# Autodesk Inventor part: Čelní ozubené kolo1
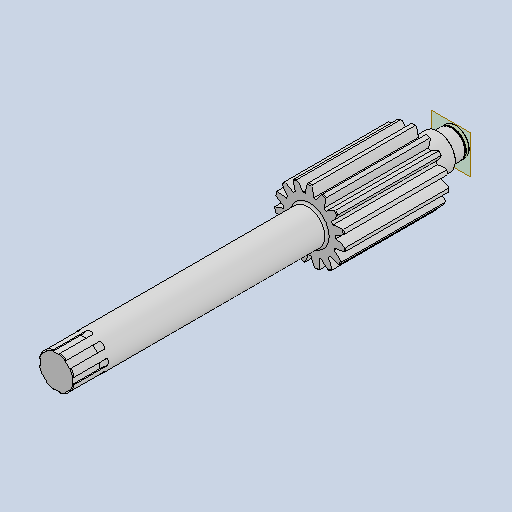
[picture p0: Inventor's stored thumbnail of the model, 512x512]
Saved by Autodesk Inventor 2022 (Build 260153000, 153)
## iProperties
CustomPartVersion: 1
Created: 2025-05
Part Number: Čelní ozubené kolo1
Material: Všeobecné
Document SubType Name: Modeling
Designer: jbart
Categories: <?xml version="1.0" encoding="UTF-16"?> <MemberInstance><Categories><FamilyTemplate><FamilyTemplateParameter ValueType="xs:double" Id="1" ObjectReferenceKey="da
Density: 1 g/cm^3
Appearance: Výchozí
Mass: 1756.11 g
Surface Area: 1642.31 cm^2
Volume: 1756.11 cm^3
Author: jbart
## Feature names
1. Extrusion1
2. Vysunutí2 [Extrusion]
3. Vysunutí3 [Extrusion]
4. Vysunutí5 [Extrusion]
5. Zaoblení1 [Fillet]
6. Vysunutí6 [Extrusion]
7. Zkosení2 [Chamfer]
8. Zaoblení3 [Fillet]
9. Tažení1
10. Kruhové pole1 [Circular Pattern]
11. Zkosení3 [Chamfer]
## Parameters: d0 = 101.98908 mm, d2 = 0, d5 = 0, d16 = 261.61692 mm, d17 = 0, d34 = 12 deg, d39 = 0, da_righttooth = 0, da_lefttooth = 0, da_dw = 90.21273 mm, da_df = 75 mm, da_da = 101.98908 mm, da_beta = 0, da_aw = 261.61692 mm, d41 = 0, d43 = 261.61692 mm, d46 = 261.61692 mm, d47 = 0, d48 = 0, d50 = 35 mm, d51 = 0, d53 = 25 mm, d54 = 0, d55 = 18 mm, d56 = 37.5 mm, d59 = 1.85 mm, d60 = 0, d64 = 1 mm, d67 = 364 mm, d68 = 0, d69 = 1 mm, d70 = 2 mm, d71 = 45 deg, d72 = 3 mm, d74 = 23 mm, d76 = 9.289 mm, d77 = 4 mm, d78 = 23 mm, d79 = 0, d80 = 0, d82 = 360 deg, d84 = 1 mm, d85 = 2 mm, d86 = 45 deg
